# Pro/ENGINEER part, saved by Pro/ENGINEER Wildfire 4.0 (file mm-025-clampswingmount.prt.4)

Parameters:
  METRIC = "NO"

Other parameters: PITCH, DRILL_DIAMETER, THREAD_DIAMETER, THREADS_PER_INCH, CBORE_DIAMETER, CBORE_DEPTH, DRILL_POINT_ANGLE, DRILL_DEPTH, THREAD_DEPTH, THREAD_LENGTH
